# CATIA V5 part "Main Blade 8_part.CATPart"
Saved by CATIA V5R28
Part number: Main Blade 8_part
Definition: design
Nomenclature: Main Blade 8_part
Source: Unknown
Bounding box of the stored display mesh (mm): x -9.987 to 1.002, y -4.846 to 1.572, z 1.529 to 7.748
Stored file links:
  D:\paraturbo-cad\STEP\Turbocompressor_for_Christophe\Main Blade 8_part.CATPart
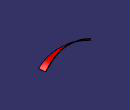
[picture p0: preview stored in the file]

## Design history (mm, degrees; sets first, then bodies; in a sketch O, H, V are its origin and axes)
Body1 "MANIFOLD_SOLID_BREP #53495" (main body)
  Solid1: solid without history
